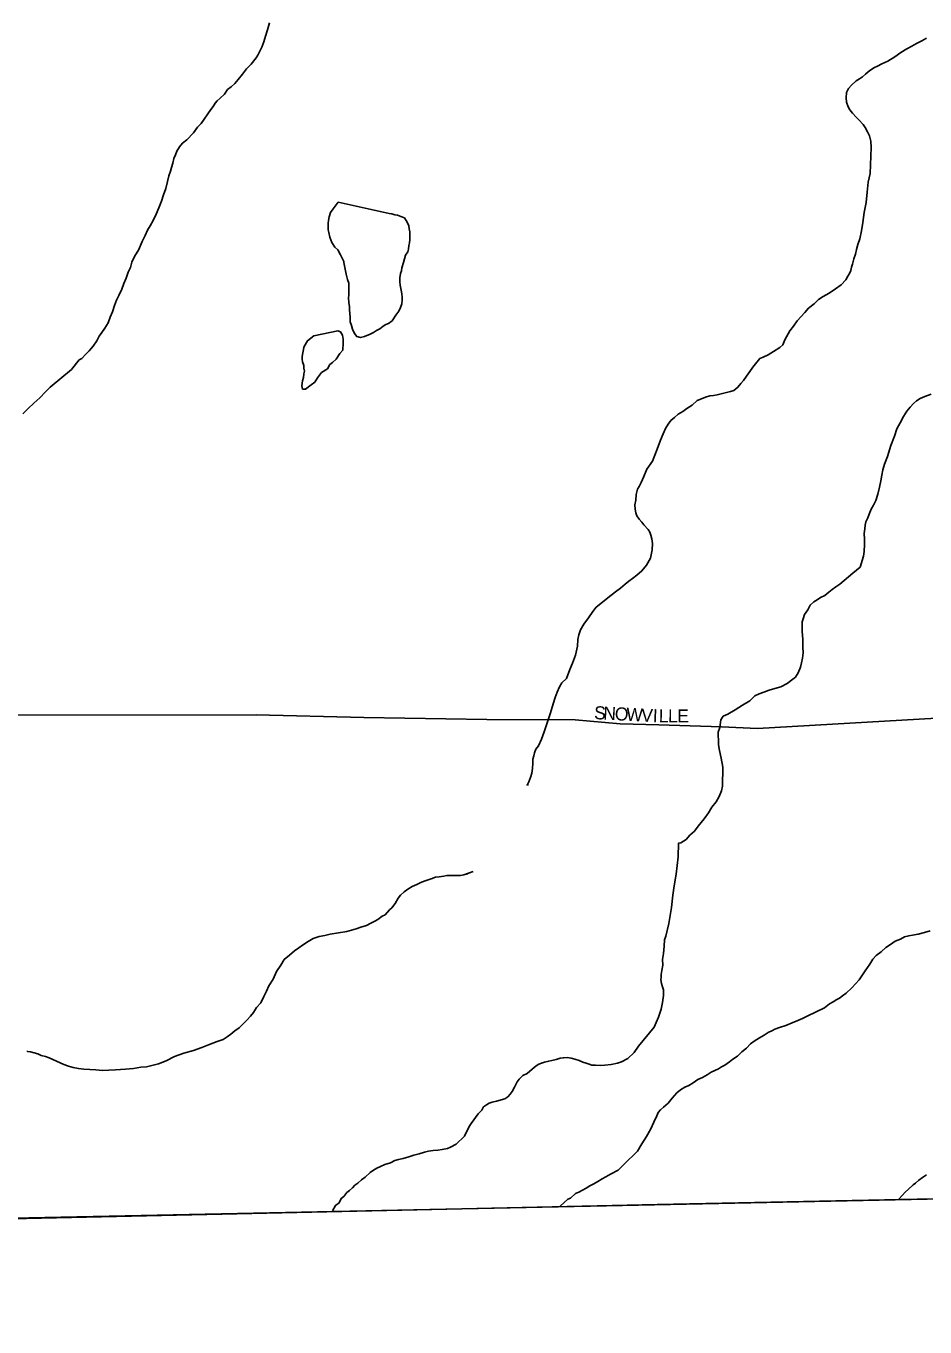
# Model space of a CAD drawing. Extents: x 2010165 to 2382125, y 1060529 to 1407316.
# Drawn here: x 2216019 to 2219461, y 1194840 to 1199820 of the extents above; entities that cross this region are included whole.
import ezdxf

# ---------------------------------------------------------------- set-up
doc = ezdxf.new("R2010")
doc.units = 0
for name, color, linetype in [('GM_X_Adjacent_County', 7, 'Continuous'), ('GM_X_City_Street', 7, 'Continuous'), ('GM_X_City_Street_Text', 7, 'Continuous'), ('GM_X_Corporation', 7, 'Continuous'), ('GM_X_County', 7, 'Continuous'), ('GM_X_Minor_Lake', 7, 'Continuous'), ('GM_X_Minor_River', 7, 'Continuous')]:
    doc.layers.add(name, color=color, linetype=linetype)

msp = doc.modelspace()

# ---------------------------------------------------------------- linework, layer by layer
at = {"layer": 'GM_X_Adjacent_County'}
msp.add_lwpolyline([(2192737.6, 1194839.7), (2198605.6, 1194974.2), (2199009.7, 1194982.8), (2204631.8, 1195039.6), (2205347.9, 1195050.5), (2205386.6, 1195051.1), (2205910.4, 1195059.1), (2205996.9, 1195060.4), (2208466.7, 1195086.6), (2214754.4, 1195227), (2218436, 1195308), (2224284, 1195428.9)], dxfattribs=at)
at = {"layer": 'GM_X_City_Street'}
msp.add_lwpolyline([(2208774.3, 1197183.4), (2214667.7, 1197181.8), (2216899.7, 1197183.8), (2217311.7, 1197172.5), (2217783.8, 1197165.3), (2218121.8, 1197163.9), (2218293.8, 1197148.2), (2218441.8, 1197144.5), (2218681.8, 1197136.8), (2218819.8, 1197131.1), (2219725.7, 1197182.9)], dxfattribs=at)
at = {"layer": 'GM_X_Corporation'}
msp.add_lwpolyline([(2225489.9, 1195453.9), (2213202.5, 1195199), (2210879.2, 1195154.6), (2209126.8, 1195115.5), (2208833.2, 1195110.6), (2205335.3, 1195051.8), (2197309.3, 1194916.9), (2196632.3, 1194905.5), (2196205.1, 1208275.6), (2197215.9, 1208288.2), (2199497, 1208304.3), (2199654.4, 1208314.4), (2199834.9, 1208326), (2199872.3, 1208332.6), (2204445.3, 1208317.3), (2204662.3, 1210529.8), (2204447.2, 1221938.7)], dxfattribs=at)
at = {"layer": 'GM_X_County'}
msp.add_lwpolyline([(2224284, 1195428.9), (2218436, 1195308), (2214754.4, 1195227), (2208466.7, 1195086.6), (2205996.9, 1195060.4), (2205910.4, 1195059.1), (2205386.6, 1195051.1), (2205347.9, 1195050.5), (2204631.8, 1195039.6), (2199009.7, 1194982.8), (2198605.6, 1194974.2), (2192737.6, 1194839.7)], dxfattribs=at)
at = {"layer": 'GM_X_Minor_Lake'}
for points in [[(2217214.4, 1199145.3), (2217194.6, 1199120.3), (2217184.8, 1199106.2), (2217179, 1199090), (2217177.2, 1199075.9), (2217175.3, 1199065.9), (2217175.5, 1199049.8), (2217175.7, 1199039.8), (2217177.8, 1199029.8), (2217182, 1199011.8), (2217186.2, 1199001.8), (2217190.3, 1198991.8), (2217200.6, 1198973.8), (2217212.7, 1198963.9), (2217223, 1198944), (2217229.2, 1198932), (2217235.3, 1198918.1), (2217236.1, 1198914.4)], [(2217236.1, 1198914.4), (2217244, 1198870), (2217250.3, 1198850), (2217254.4, 1198836), (2217254.6, 1198825.9), (2217254.7, 1198815.9), (2217254.9, 1198801.8), (2217255, 1198789.8), (2217253.2, 1198779.7), (2217255.4, 1198761.7), (2217257.6, 1198745.6), (2217257.8, 1198733.6), (2217258, 1198719.6), (2217260.2, 1198705.5), (2217260.4, 1198687.4), (2217264.6, 1198673.4), (2217268.8, 1198659.4), (2217277, 1198643.5), (2217285.2, 1198631.6), (2217299.2, 1198627.7), (2217315.2, 1198631.9), (2217337.1, 1198640.2), (2217349.1, 1198646.4), (2217361, 1198654.6), (2217372.9, 1198660.8), (2217386.8, 1198671), (2217396.8, 1198677.1), (2217406.7, 1198681.3), (2217420.6, 1198691.5), (2217434.4, 1198713.8), (2217446.2, 1198728), (2217452, 1198742.1), (2217457.8, 1198756.2), (2217459.6, 1198772.3), (2217459.5, 1198782.4), (2217457.3, 1198794.4), (2217455.2, 1198808.4), (2217450.9, 1198828.4), (2217450.7, 1198840.5), (2217450.5, 1198856.5), (2217452.3, 1198872.6), (2217456.2, 1198882.7), (2217458, 1198894.8), (2217463.8, 1198914.9), (2217471.4, 1198943.2), (2217481.3, 1198955.3), (2217483.2, 1198965.4), (2217485, 1198979.5), (2217486.9, 1198989.5), (2217488.7, 1199001.6), (2217488.5, 1199017.7), (2217488.3, 1199031.7), (2217486.2, 1199043.7), (2217484, 1199055.8), (2217477.8, 1199069.7), (2217467.6, 1199085.7), (2217453.5, 1199091.5), (2217441.4, 1199095.4), (2217431.4, 1199097.2), (2217419.3, 1199101.1), (2217409.3, 1199103), (2217214.4, 1199145.3)], [(2217082.3, 1198589.3), (2217075.8, 1198554.6), (2217075.9, 1198544.6), (2217078, 1198534.5), (2217082.2, 1198520.5), (2217082.4, 1198510.5), (2217084.5, 1198498.5), (2217082.6, 1198488.4), (2217080.8, 1198474.3), (2217077, 1198462.2), (2217075.2, 1198442.1), (2217077.4, 1198430.1), (2217089.4, 1198430.3), (2217111.2, 1198446.6), (2217125.1, 1198456.8), (2217134.9, 1198473), (2217150.7, 1198493.3), (2217172.6, 1198507.6), (2217182.4, 1198523.8), (2217192.3, 1198532), (2217206.1, 1198544.2), (2217219.9, 1198566.5), (2217231.7, 1198578.7), (2217233.4, 1198606.8), (2217233.2, 1198620.8), (2217231, 1198636.9), (2217222.8, 1198648.8), (2217212.7, 1198652.7), (2217120.8, 1198633.5)], [(2217120.8, 1198633.5), (2217097, 1198615.1), (2217120.8, 1198633.5), (2217097, 1198615.1), (2217083.3, 1198592.8), (2217082.3, 1198589.3)]]:
    msp.add_lwpolyline(points, dxfattribs=at)
at = {"layer": 'GM_X_Minor_River'}
for points in [[(2216950.9, 1199832.1), (2216943.3, 1199805.9), (2216935.6, 1199781.7), (2216929.9, 1199759.5), (2216922.1, 1199739.3), (2216912.3, 1199721.1), (2216906.5, 1199709), (2216900.6, 1199698.9), (2216880.9, 1199674.6), (2216863.1, 1199656.3), (2216847.3, 1199636), (2216831.5, 1199615.7), (2216817.7, 1199599.5), (2216803.9, 1199587.2), (2216790, 1199577), (2216778.2, 1199558.8), (2216762.3, 1199544.5), (2216750.5, 1199534.3), (2216742.6, 1199524.2), (2216734.7, 1199512.1), (2216726.9, 1199499.9), (2216689.5, 1199447.2), (2216675.6, 1199433), (2216659.9, 1199410.7), (2216634.2, 1199384.3), (2216618.3, 1199372), (2216606.5, 1199357.8), (2216596.7, 1199341.6), (2216590.9, 1199327.5), (2216585, 1199313.4), (2216581.3, 1199295.2), (2216575.5, 1199279.1), (2216571.6, 1199265), (2216565.9, 1199246.9), (2216560.1, 1199224.7), (2216554.5, 1199198.5), (2216544.8, 1199174.3)], [(2219466.3, 1199773.8), (2219448.4, 1199763.5), (2219428.5, 1199753.2), (2219410.6, 1199742.9), (2219390.7, 1199732.6), (2219368.8, 1199718.3), (2219345, 1199701.9), (2219319.1, 1199685.6), (2219295.2, 1199675.2), (2219279.3, 1199667), (2219267.4, 1199660.8), (2219253.5, 1199652.6), (2219243.6, 1199644.4), (2219233.6, 1199636.3), (2219221.7, 1199626.1), (2219209.8, 1199617.9), (2219197.9, 1199609.7), (2219180.1, 1199593.4), (2219168.2, 1199581.2), (2219160.4, 1199565.1), (2219158.7, 1199545), (2219160.9, 1199528.9), (2219167.1, 1199510.9), (2219173.3, 1199499), (2219183.5, 1199487.1), (2219197.7, 1199471.2), (2219207.9, 1199461.2), (2219224.1, 1199443.4), (2219232.3, 1199431.4), (2219240.5, 1199415.5), (2219248.7, 1199399.5), (2219253, 1199379.5), (2219255.3, 1199355.4), (2219250.6, 1199255), (2219243, 1199222.8), (2219239.5, 1199184.6), (2219236, 1199144.4), (2219228.5, 1199106.1), (2219223, 1199067.9), (2219217.4, 1199035.7), (2219211.8, 1199005.5), (2219204.1, 1198983.3), (2219198.3, 1198965.2), (2219194.5, 1198947), (2219188.7, 1198928.9), (2219183, 1198908.8), (2219179.1, 1198896.6), (2219177.3, 1198884.6), (2219171.4, 1198872.5), (2219165.6, 1198862.3), (2219157.7, 1198848.2), (2219139.9, 1198829.9), (2219118.1, 1198813.5), (2219094.3, 1198797.2), (2219070.4, 1198784.8), (2219052.5, 1198772.6), (2219036.7, 1198756.3), (2219014.9, 1198739.9), (2219001.1, 1198723.7), (2218971.4, 1198691.2), (2218957.7, 1198670.9), (2218943.9, 1198652.7), (2218924.3, 1198618.3), (2218916.5, 1198600.1), (2218904.6, 1198589.9), (2218880.8, 1198573.6), (2218860.9, 1198561.3), (2218841, 1198553), (2218829.1, 1198546.8), (2218811.3, 1198526.5), (2218801.4, 1198514.3), (2218789.6, 1198498.1), (2218777.8, 1198479.9), (2218766, 1198463.7), (2218756.2, 1198451.5), (2218744.3, 1198437.3), (2218728.5, 1198425.1), (2218716.5, 1198420.9), (2218664.6, 1198408.2), (2218650.6, 1198406), (2218636.6, 1198403.8), (2218620.6, 1198399.6), (2218604.6, 1198393.4), (2218588.7, 1198387.1), (2218568.9, 1198368.8), (2218549, 1198356.5), (2218533.1, 1198344.3), (2218515.3, 1198334), (2218501.4, 1198321.8), (2218487.5, 1198309.5), (2218477.7, 1198295.4)], [(2216544.8, 1199174.3), (2216537.1, 1199150.1), (2216527.4, 1199123.9), (2216517.7, 1199099.7), (2216506, 1199075.4), (2216494.2, 1199055.2), (2216484.4, 1199039), (2216474.7, 1199018.8), (2216463, 1198994.6), (2216449.3, 1198962.2), (2216435.6, 1198940), (2216423.9, 1198915.7), (2216418.2, 1198895.6), (2216410.4, 1198877.4), (2216402.6, 1198855.2), (2216392.9, 1198835), (2216385.2, 1198812.8), (2216373.5, 1198788.6), (2216365.7, 1198770.4), (2216357.9, 1198750.2), (2216350.2, 1198726.1), (2216340.5, 1198705.8), (2216332.7, 1198683.7), (2216321, 1198663.4), (2216309.2, 1198647.2), (2216299.4, 1198633), (2216289.6, 1198614.8), (2216275.8, 1198594.6), (2216260, 1198576.3), (2216246.2, 1198562.1), (2216232.3, 1198547.8), (2216222.4, 1198541.7), (2216192.8, 1198505.2), (2216111.5, 1198437.9), (2216093.7, 1198419.6), (2216072, 1198397.2), (2216048.2, 1198376.8), (2216026.4, 1198356.5), (2216006.7, 1198336.1)], [(2219484, 1198410.6), (2219460.1, 1198402.3), (2219442.2, 1198394), (2219428.2, 1198385.8), (2219416.3, 1198375.6), (2219404.5, 1198361.4), (2219390.7, 1198345.1), (2219378.9, 1198324.9), (2219365.2, 1198300.6), (2219353.5, 1198278.4), (2219343.8, 1198250.2), (2219330.3, 1198213.9), (2219316.8, 1198171.5), (2219305.2, 1198143.3), (2219299.4, 1198121.1), (2219295.7, 1198101), (2219292, 1198078.8), (2219286.3, 1198054.7), (2219280.6, 1198028.5), (2219272.9, 1198004.3), (2219263.1, 1197986.1), (2219255.3, 1197969.9), (2219247.5, 1197951.8), (2219241.7, 1197937.6), (2219233.9, 1197921.5), (2219232.1, 1197909.4), (2219230.2, 1197895.3), (2219228.5, 1197877.2), (2219228.8, 1197855.1), (2219229, 1197835.1), (2219227.4, 1197808.9), (2219225.6, 1197790.8), (2219212.1, 1197748.5), (2219184.4, 1197726.1)], [(2218477.7, 1198295.4), (2218467.9, 1198279.2), (2218458.1, 1198259), (2218448.4, 1198234.7), (2218434.8, 1198200.4), (2218417.4, 1198154), (2218395.8, 1198123.6), (2218384.1, 1198095.4), (2218374.4, 1198073.2), (2218366.6, 1198057), (2218360.7, 1198046.9), (2218355, 1198026.7), (2218353.2, 1198004.6), (2218349.5, 1197986.5), (2218351.7, 1197970.5), (2218353.9, 1197956.4), (2218358, 1197944.4), (2218366.2, 1197932.5), (2218376.4, 1197920.6), (2218384.5, 1197910.6), (2218400.8, 1197892.8), (2218406.9, 1197882.8), (2218411.1, 1197870.8), (2218415.3, 1197856.8), (2218417.5, 1197838.8), (2218415.8, 1197814.7), (2218410.2, 1197782.5), (2218394.5, 1197756.2), (2218376.8, 1197733.8), (2218357, 1197717.5), (2218341.1, 1197705.3), (2218327.2, 1197695.1), (2218313.3, 1197682.8), (2218295.5, 1197668.6), (2218275.6, 1197654.2), (2218257.8, 1197640), (2218202.3, 1197595.1), (2218188.5, 1197578.8), (2218172.8, 1197554.5), (2218155, 1197530.2), (2218141.3, 1197508), (2218135.5, 1197489.8), (2218131.8, 1197471.7), (2218130.1, 1197445.6), (2218122.5, 1197411.3), (2218110.9, 1197381.1), (2218101.2, 1197356.8), (2218087.6, 1197322.5), (2218069.8, 1197306.2), (2218062, 1197290.1), (2218052.2, 1197269.9), (2218044.5, 1197249.7), (2218036.8, 1197225.5), (2218027.2, 1197191.2), (2218013.7, 1197152.9), (2218002.1, 1197118.6), (2217992.5, 1197090.4), (2217980.8, 1197064.1), (2217970.9, 1197052), (2217965.1, 1197037.8), (2217963.2, 1197025.8), (2217959.4, 1197013.7), (2217959.6, 1196997.6), (2217957.8, 1196977.5), (2217956.1, 1196959.4), (2217952.2, 1196947.3), (2217948.4, 1196937.2), (2217944.5, 1196927.1), (2217938.6, 1196917), (2217936.6, 1196915), (2217942.6, 1196915.1)], [(2219184.4, 1197726.1), (2219134.8, 1197683.3), (2219118.9, 1197673), (2219105, 1197662.8), (2219093.1, 1197652.6), (2219077.3, 1197640.4), (2219061.4, 1197632.1), (2219047.4, 1197623.9), (2219035.5, 1197615.7), (2219021.7, 1197603.5), (2219011.9, 1197585.3), (2219000.1, 1197567.1), (2218994.3, 1197551), (2218990.4, 1197538.9), (2218990.6, 1197526.8), (2218990.9, 1197502.7), (2218993.3, 1197472.6), (2218993.7, 1197442.5), (2218994, 1197420.4), (2218992.2, 1197400.3), (2218988.5, 1197382.2), (2218984.7, 1197366.1), (2218974.9, 1197343.9), (2218965.1, 1197327.7), (2218955.2, 1197319.6), (2218933.4, 1197303.2), (2218909.5, 1197290.8), (2218885.6, 1197284.5), (2218863.6, 1197278.2), (2218843.7, 1197269.9), (2218825.7, 1197263.7), (2218809.8, 1197255.4), (2218790, 1197237.1), (2218762.2, 1197220.7), (2218734.3, 1197202.3), (2218706.5, 1197185.8), (2218688.6, 1197177.6), (2218678.7, 1197163.4), (2218675.1, 1197135.2), (2218669.3, 1197117.1), (2218669.5, 1197103.1), (2218669.7, 1197087), (2218670, 1197068.9), (2218674.3, 1197046.9), (2218680.7, 1197016.8), (2218687.1, 1196982.8), (2218686, 1196910.5), (2218682.3, 1196892.4), (2218672.5, 1196870.2), (2218660.8, 1196849.9), (2218645, 1196829.6), (2218631.3, 1196807.4), (2218615.5, 1196785.1), (2218603.7, 1196770.9), (2218591.9, 1196756.7), (2218578.1, 1196738.4), (2218560.3, 1196722.1), (2218546.4, 1196705.9), (2218526.6, 1196693.6), (2218516.6, 1196691.5), (2218515.3, 1196639.2), (2218508.1, 1196572.9), (2218500.7, 1196528.6), (2218495.1, 1196492.4), (2218489.7, 1196446.1), (2218480.5, 1196383.8), (2218469.1, 1196335.4), (2218463.3, 1196321.3), (2218461.6, 1196297.2), (2218460, 1196269.1), (2218456.2, 1196246.9), (2218456.5, 1196224.8), (2218452.8, 1196204.7), (2218451, 1196188.6), (2218451.1, 1196178.6), (2218449.2, 1196168.5), (2218451.4, 1196154.5), (2218455.6, 1196142.5), (2218459.8, 1196130.5), (2218460, 1196108.4), (2218456.4, 1196082.3), (2218450.7, 1196056.1), (2218441.1, 1196025.9), (2218431.3, 1196005.6), (2218423.5, 1195987.5), (2218364.4, 1195914.4), (2218346.7, 1195890.1), (2218322.9, 1195867.7), (2218299, 1195855.4), (2218283.1, 1195849.1), (2218259.1, 1195844.8), (2218235.1, 1195842.5), (2218217.1, 1195840.3), (2218199, 1195842.1), (2218185, 1195841.9), (2218174.9, 1195845.8), (2218162.9, 1195849.6), (2218150.8, 1195853.5), (2218136.7, 1195859.3), (2218120.6, 1195865.1), (2218106.5, 1195869)], [(2217730.6, 1196583.1), (2217694.7, 1196570.5), (2217710.6, 1196574.8), (2217694.7, 1196570.5), (2217682.7, 1196568.4), (2217670.6, 1196568.2), (2217656.6, 1196568.1), (2217642.6, 1196567.9), (2217630.6, 1196567.7), (2217618.6, 1196565.6), (2217600.6, 1196563.3), (2217586.6, 1196561.1), (2217570.6, 1196554.9), (2217550.7, 1196548.6), (2217532.7, 1196542.4), (2217514.8, 1196534.1), (2217496.9, 1196525.9), (2217481, 1196515.6), (2217467.1, 1196505.4), (2217453.2, 1196493.2), (2217443.4, 1196481), (2217431.6, 1196460.8), (2217419.8, 1196444.6), (2217409.9, 1196436.4), (2217394.1, 1196418.1), (2217382.2, 1196411.9), (2217366.3, 1196399.7), (2217354.3, 1196393.5), (2217338.4, 1196385.3), (2217322.5, 1196377), (2217300.5, 1196370.8), (2217282.6, 1196364.5), (2217264.6, 1196358.2), (2217246.7, 1196354), (2217182.7, 1196343.1), (2217162.7, 1196338.9), (2217140.7, 1196334.6), (2217118.8, 1196326.3), (2217098.9, 1196316), (2217077, 1196301.6), (2217063.1, 1196291.4), (2217047.3, 1196279.2), (2217027.5, 1196262.8), (2217007.6, 1196246.5), (2216993.9, 1196224.3), (2216978.2, 1196200), (2216964.5, 1196171.7), (2216948.8, 1196145.4), (2216939.1, 1196125.2), (2216929.3, 1196105), (2216917.6, 1196080.7), (2216901.8, 1196062.4), (2216890, 1196044.2), (2216878.2, 1196030), (2216864.4, 1196013.8), (2216848.5, 1195999.5), (2216834.7, 1195985.3), (2216818.8, 1195973), (2216803, 1195960.8), (2216789.1, 1195950.6), (2216773.2, 1195940.3), (2216751.2, 1195932), (2216717.3, 1195919.5), (2216691.4, 1195909.2), (2216659.5, 1195898.7), (2216623.6, 1195888.2), (2216587.7, 1195875.7), (2216555.8, 1195859.2), (2216525.9, 1195846.8), (2216500, 1195840.5), (2216480, 1195836.2), (2216458, 1195833.9), (2216430, 1195829.5), (2216400, 1195827.1), (2216361.9, 1195824.6), (2216335.9, 1195822.3), (2216311.9, 1195822), (2216285.8, 1195823.7), (2216263.7, 1195825.4), (2216239.7, 1195827.1), (2216219.6, 1195828.8), (2216199.5, 1195832.6), (2216181.4, 1195838.4), (2216163.3, 1195844.2), (2216106.9, 1195869.6), (2216092.8, 1195875.4), (2216076.7, 1195879.2), (2216064.6, 1195885.1), (2216050.5, 1195888.9), (2216036.5, 1195892.8), (2216024.4, 1195894.6), (2216022.4, 1195896.6)], [(2219480.7, 1196356.4), (2219458.7, 1196350.1), (2219434.8, 1196343.8), (2219412.8, 1196339.4), (2219398.8, 1196337.3), (2219382.8, 1196333), (2219366.9, 1196324.8), (2219347, 1196316.5), (2219329.1, 1196304.2), (2219311.2, 1196292), (2219293.4, 1196275.7), (2219273.5, 1196261.4), (2219261.7, 1196247.2), (2219249.9, 1196228.9), (2219232.2, 1196202.6), (2219208.6, 1196168.2), (2219181, 1196137.7), (2219159.2, 1196117.3), (2219145.3, 1196107.1), (2219133.4, 1196098.9), (2219123.5, 1196092.8), (2219109.5, 1196084.6), (2219095.6, 1196076.4), (2219075.8, 1196062.1), (2219010.1, 1196029.1), (2218992.1, 1196020.8), (2218974.2, 1196012.6), (2218952.3, 1196004.3), (2218928.4, 1195993.9), (2218904.4, 1195985.6), (2218886.5, 1195979.3), (2218876.5, 1195975.2)], [(2218876.5, 1195975.2), (2218860.6, 1195966.9), (2218844.7, 1195956.7), (2218826.8, 1195946.4), (2218806.9, 1195934.1), (2218793, 1195923.9), (2218777.2, 1195907.7), (2218759.4, 1195893.4), (2218743.6, 1195877.1), (2218725.7, 1195864.8), (2218711.8, 1195854.6), (2218693.9, 1195842.3), (2218682, 1195836.2), (2218670.1, 1195828), (2218656.1, 1195821.8), (2218642.2, 1195815.6), (2218626.3, 1195805.3), (2218608.4, 1195795.1), (2218590.5, 1195786.8), (2218572.6, 1195774.5), (2218556.7, 1195764.3), (2218540.7, 1195758.1), (2218524.8, 1195747.8), (2218511, 1195735.6), (2218493.2, 1195715.3), (2218477.4, 1195697), (2218459.6, 1195680.7), (2218447.7, 1195670.5), (2218439.8, 1195660.4), (2218434, 1195648.3), (2218422.3, 1195624), (2218410.6, 1195597.8), (2218394.9, 1195569.4), (2218377.3, 1195541.1), (2218359.6, 1195512.8), (2218341.8, 1195494.5), (2218326, 1195480.2), (2218286.4, 1195439.6), (2218256.5, 1195425.1), (2218238.6, 1195414.8), (2218224.7, 1195406.6), (2218208.8, 1195396.4), (2218192.9, 1195388.2), (2218177, 1195379.9), (2218163.1, 1195371.7), (2218149.2, 1195363.5), (2218135.2, 1195355.3), (2218123.3, 1195351.1), (2218103.5, 1195332.8), (2218093.5, 1195328.7), (2218063.5, 1195302.6)], [(2218106.5, 1195869), (2218090.5, 1195870.8), (2218076.4, 1195870.6), (2218064.4, 1195868.4), (2218048.5, 1195864.2), (2218032.5, 1195860), (2218020.5, 1195857.8), (2218004.5, 1195853.6), (2217992.6, 1195849.5), (2217982.6, 1195845.3), (2217972.7, 1195839.2), (2217956.8, 1195826.9), (2217937, 1195810.6), (2217921, 1195802.4), (2217907.2, 1195788.1), (2217899.3, 1195778), (2217889.6, 1195757.8), (2217879.8, 1195741.6), (2217871.9, 1195731.4), (2217864, 1195721.3), (2217852.1, 1195713.1), (2217820.1, 1195704.7), (2217804.2, 1195700.5), (2217792.2, 1195696.3), (2217782.2, 1195690.1), (2217770.3, 1195682), (2217764.5, 1195669.8), (2217750.6, 1195655.6), (2217723.1, 1195619.1), (2217715.2, 1195607), (2217697.6, 1195570.6), (2217666, 1195540.1), (2217644.1, 1195527.8), (2217632.1, 1195523.6), (2217612.2, 1195519.3), (2217596.2, 1195517.1), (2217578.2, 1195514.9), (2217560.2, 1195512.6), (2217544.2, 1195508.4), (2217524.2, 1195502.1), (2217504.2, 1195497.8), (2217484.3, 1195491.6), (2217462.3, 1195485.3), (2217444.4, 1195481), (2217430.4, 1195476.8), (2217414.5, 1195468.6), (2217392.5, 1195462.3), (2217376.6, 1195454.1), (2217362.6, 1195447.9), (2217348.7, 1195439.6), (2217336.8, 1195431.5), (2217317, 1195413.1), (2217303.1, 1195402.9), (2217289.2, 1195390.7), (2217277.3, 1195382.5), (2217269.4, 1195372.4), (2217257.6, 1195362.2), (2217247.6, 1195354), (2217235.8, 1195339.8), (2217225.9, 1195331.7), (2217218.1, 1195315.5), (2217204.2, 1195305.3), (2217192.4, 1195284.6)], [(2219466.8, 1195422.5), (2219450.9, 1195412.2), (2219437, 1195402), (2219425.1, 1195389.8), (2219415.2, 1195383.7), (2219397.4, 1195367.4), (2219385.5, 1195355.2), (2219373.6, 1195343), (2219361, 1195329.4)]]:
    msp.add_lwpolyline(points, dxfattribs=at)

# ---------------------------------------------------------------- texts
at = {"layer": 'GM_X_City_Street_Text'}
for s, rotation, p in [('S', 356.993, (2218193, 1197167)), ('N', 357.0206, (2218228.2, 1197165.2)), ('O', 357.0206, (2218272.2, 1197162.9)), ('W', 357.0154, (2218316.1, 1197160.6)), ('V', 357.0206, (2218373.2, 1197157.6)), ('I', 357.6817, (2218417.8, 1197155.3)), ('L', 359.2795, (2218441.3, 1197154.3)), ('L', 359.9457, (2218477.1, 1197153.9)), ('E', 359.9956, (2218512.4, 1197153.9))]:
    msp.add_text(s, height=50, rotation=rotation, dxfattribs=at).set_placement(p)

doc.saveas('drawing.dxf')
